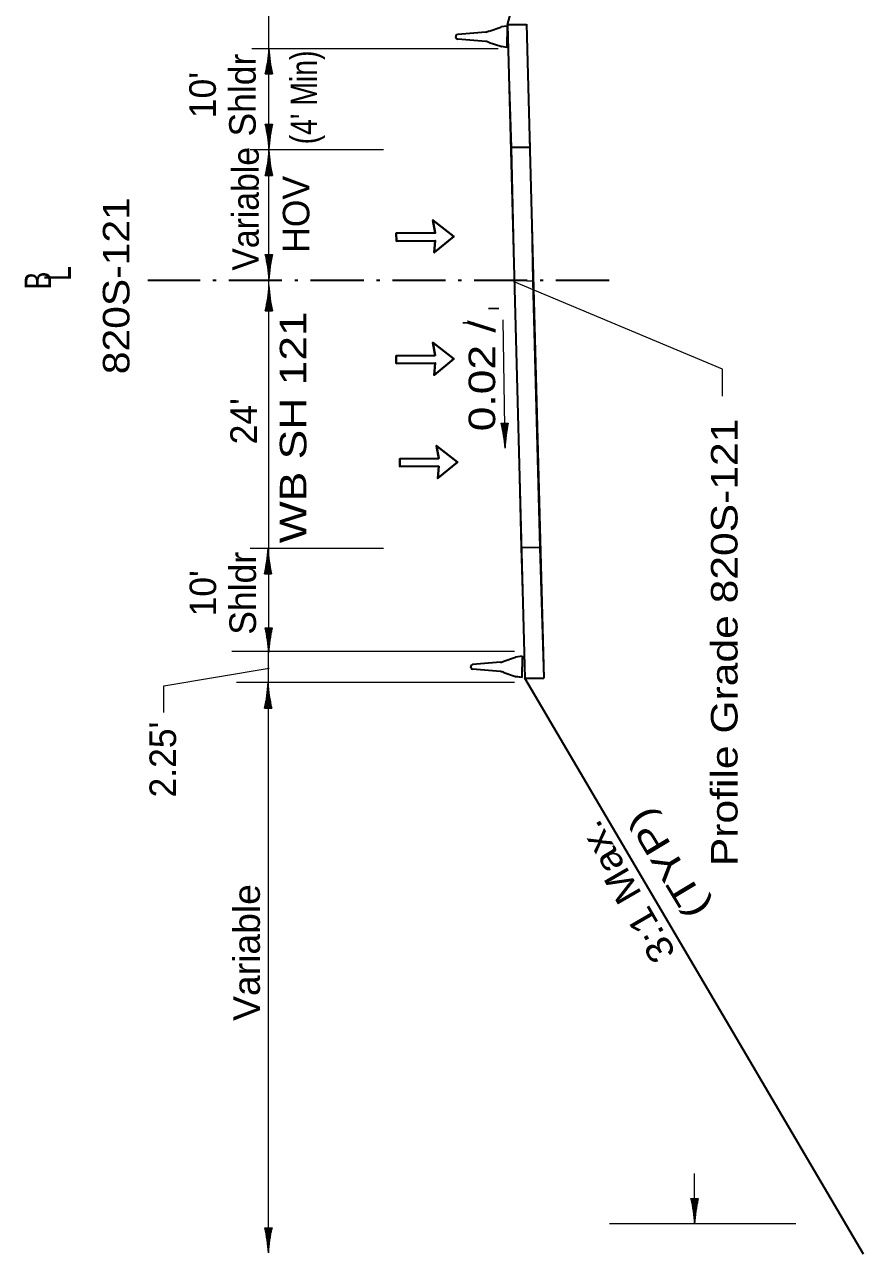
# Model space of a CAD drawing. Extents: x 2363427 to 2368559, y 6957299 to 6980140.
# Drawn here: x 2364081 to 2364523, y 6964609 to 6965257 of the extents above; entities that cross this region are included whole.
import ezdxf
from ezdxf.enums import TextEntityAlignment as Align

# ---------------------------------------------------------------- set-up
doc = ezdxf.new("R2010")
doc.units = 0
doc.header["$LTSCALE"] = 5.6
doc.linetypes.add('DOT_DASHED', pattern=[7.7, 5, -1.2, 0.3, -1.2])
for name, color, linetype, lineweight in [('1', 7, 'Continuous', 13), ('3', 7, 'Continuous', 35), ('4', 7, 'Continuous', 13), ('40', 7, 'Continuous', 35), ('8', 7, 'Continuous', 13)]:
    doc.layers.add(name, color=color, linetype=linetype, lineweight=lineweight)

msp = doc.modelspace()

# ---------------------------------------------------------------- linework, layer by layer
at = {"layer": '1'}
for p, q in [((2364432.195, 6964638.052), (2364436.025, 6964638.052)), ((2364432.545, 6964638.052), (2364432.545, 6964636.466)), ((2364433.045, 6964638.052), (2364433.045, 6964633.776)), ((2364433.545, 6964638.052), (2364433.545, 6964630.702)), ((2364434.045, 6964638.052), (2364434.045, 6964625.488)), ((2364434.545, 6964638.052), (2364434.545, 6964629.442)), ((2364435.045, 6964638.052), (2364435.045, 6964633.19)), ((2364435.545, 6964638.052), (2364435.545, 6964635.67))]:
    msp.add_line(p, q, dxfattribs=at)
for centre, start, end in [((2364361.987, 6964621.158), 2.84356, 13.52961), ((2364506.234, 6964621.158), 166.47039, 177.15644)]:
    msp.add_arc(centre, 72.212, start, end, dxfattribs=at)
at = {"layer": '3'}
for p, q in [((2364323.944, 6965253.408), (2364309.24, 6965252.173)), ((2364325.732, 6965253.937), (2364331.846, 6965255.978)), ((2364332.01, 6965256.044), (2364332.02, 6965256.068)), ((2364335.283, 6965256.556), (2364332.02, 6965256.068)), ((2364335.283, 6965256.556), (2364332.217, 6965256.098)), ((2364335.283, 6965256.556), (2364335.283, 6965250.932)), ((2364345.398, 6965257.606), (2364354.58, 6964912.562)), ((2364308.213, 6965251.332), (2364308.213, 6965250.932)), ((2364308.213, 6965250.531), (2364308.213, 6965250.932)), ((2364323.944, 6965248.455), (2364309.24, 6965249.69)), ((2364325.732, 6965247.926), (2364331.846, 6965245.884)), ((2364332.01, 6965245.82), (2364332.02, 6965245.794)), ((2364335.283, 6965245.306), (2364332.02, 6965245.794)), ((2364335.283, 6965245.306), (2364332.217, 6965245.766)), ((2364335.283, 6965245.306), (2364335.283, 6965250.932)), ((2364347.589, 6965192.45), (2364337.588, 6965192.45)), ((2364343.957, 6964943.654), (2364343.793, 6964943.962)), ((2364333.538, 6964921.55), (2364339.651, 6964923.592)), ((2364339.816, 6964923.656), (2364339.826, 6964923.682)), ((2364343.088, 6964924.17), (2364339.826, 6964923.682)), ((2364343.088, 6964924.17), (2364340.022, 6964923.71)), ((2364343.088, 6964924.17), (2364343.088, 6964918.544)), ((2364316.018, 6964918.945), (2364316.018, 6964918.544)), ((2364316.018, 6964918.144), (2364316.018, 6964918.544)), ((2364331.749, 6964921.021), (2364317.046, 6964919.786)), ((2364331.749, 6964916.068), (2364317.046, 6964917.303)), ((2364333.538, 6964915.539), (2364339.651, 6964913.498)), ((2364343.088, 6964912.92), (2364343.088, 6964918.544)), ((2364339.816, 6964913.432), (2364339.826, 6964913.408)), ((2364343.088, 6964912.92), (2364339.826, 6964913.408)), ((2364343.088, 6964912.92), (2364340.022, 6964913.378)), ((2364344.576, 6964912.562), (2364354.579, 6964912.562)), ((2364523.11, 6964608.848), (2364344.609, 6964912.542))]:
    msp.add_line(p, q, dxfattribs=at)
at = {"layer": '3', "linetype": 'DOT_DASHED'}
msp.add_line((2364388.994, 6965122.286), (2364145.785, 6965122.286), dxfattribs=at)
at = {"layer": '3', "lineweight": 13}
for p, q in [((2364448.885, 6965075.502), (2364338.95, 6965121.619)), ((2364448.885, 6965061.274), (2364448.885, 6965075.502)), ((2364154.244, 6964908.479), (2364209.681, 6964917.845)), ((2364154.244, 6964894.43), (2364154.244, 6964908.479))]:
    msp.add_line(p, q, dxfattribs=at)
at = {"layer": '3'}
for points in [[(2364335.405, 6965257.22), (2364342.45, 6965282.965), (2364333.872, 6965304.046)], [(2364345.408, 6965257.22), (2364335.405, 6965257.22), (2364344.576, 6964912.562)]]:
    msp.add_lwpolyline(points, dxfattribs=at)
at = {"layer": '3', "lineweight": 13}
for points in [[(2364337.588, 6965192.45), (2364347.589, 6965192.45), (2364345.408, 6965257.22), (2364335.405, 6965257.22)], [(2364339.137, 6965122.445), (2364348.845, 6965121.956), (2364347.589, 6965192.45), (2364337.588, 6965192.45)], [(2364342.471, 6964981.594), (2364352.472, 6964981.594), (2364348.845, 6965121.956), (2364339.137, 6965122.445)], [(2364344.576, 6964912.562), (2364354.58, 6964912.562), (2364352.472, 6964981.594), (2364342.471, 6964981.594)]]:
    msp.add_lwpolyline(points, close=True, dxfattribs=at)
at = {"layer": '3'}
for centre, radius, start, end in [((2364309.361, 6965250.979), 1.2, 95.72178, 162.90786), ((2364323.445, 6965258.384), 5, 275.73538, 297.22872), ((2364332.396, 6965254.911), 1.2, 98.51269, 117.22516), ((2364309.361, 6965250.884), 1.2, 197.09214, 264.27822), ((2364323.445, 6965243.48), 5, 62.77128, 84.26462), ((2364332.396, 6965246.952), 1.2, 242.77484, 261.48731), ((2364331.25, 6964925.997), 5, 275.73538, 297.22872), ((2364340.201, 6964922.524), 1.2, 98.51269, 117.22516), ((2364317.166, 6964918.592), 1.2, 95.72178, 162.90786), ((2364317.166, 6964918.497), 1.2, 197.09214, 264.27822), ((2364331.25, 6964911.093), 5, 62.77128, 84.26462), ((2364340.201, 6964914.565), 1.2, 242.77484, 261.48731)]:
    msp.add_arc(centre, radius, start, end, dxfattribs=at)
at = {"layer": '4'}
for p, q in [((2364209.647, 6964926.644), (2364209.647, 6965291.985)), ((2364209.583, 6965231.306), (2364209.583, 6965243.87)), ((2364210.083, 6965231.306), (2364210.083, 6965239.914)), ((2364330.544, 6965244.616), (2364233.477, 6965244.616)), ((2364208.083, 6965231.306), (2364208.083, 6965232.89)), ((2364208.583, 6965231.306), (2364208.583, 6965235.582)), ((2364209.083, 6965231.306), (2364209.083, 6965238.656)), ((2364210.583, 6965231.306), (2364210.583, 6965236.168)), ((2364211.083, 6965231.306), (2364211.083, 6965233.686)), ((2364207.733, 6965231.306), (2364211.563, 6965231.306)), ((2364207.733, 6965204.804), (2364211.563, 6965204.804)), ((2364208.083, 6965204.804), (2364208.083, 6965203.218)), ((2364208.583, 6965204.804), (2364208.583, 6965200.528)), ((2364209.083, 6965204.804), (2364209.083, 6965197.454)), ((2364209.583, 6965204.804), (2364209.583, 6965192.24)), ((2364210.083, 6965204.804), (2364210.083, 6965196.194)), ((2364210.583, 6965204.804), (2364210.583, 6965199.942)), ((2364211.083, 6965204.804), (2364211.083, 6965202.422)), ((2364269.98, 6965191.292), (2364199.828, 6965191.292)), ((2364209.583, 6965177.66), (2364209.583, 6965190.224)), ((2364208.583, 6965177.66), (2364208.583, 6965181.936)), ((2364209.083, 6965177.66), (2364209.083, 6965185.01)), ((2364210.083, 6965177.66), (2364210.083, 6965186.27)), ((2364210.583, 6965177.66), (2364210.583, 6965182.522)), ((2364207.733, 6965177.66), (2364211.563, 6965177.66)), ((2364208.083, 6965177.66), (2364208.083, 6965179.246)), ((2364211.083, 6965177.66), (2364211.083, 6965180.042)), ((2364207.733, 6965136.08), (2364211.563, 6965136.08)), ((2364208.083, 6965136.08), (2364208.083, 6965134.494)), ((2364208.583, 6965136.08), (2364208.583, 6965131.804)), ((2364209.083, 6965136.08), (2364209.083, 6965128.73)), ((2364209.583, 6965136.08), (2364209.583, 6965123.516)), ((2364210.083, 6965136.08), (2364210.083, 6965127.47)), ((2364210.583, 6965136.08), (2364210.583, 6965131.218)), ((2364211.083, 6965136.08), (2364211.083, 6965133.698)), ((2364209.583, 6965106.334), (2364209.583, 6965118.898)), ((2364208.583, 6965106.334), (2364208.583, 6965110.61)), ((2364209.083, 6965106.334), (2364209.083, 6965113.684)), ((2364210.083, 6965106.334), (2364210.083, 6965114.942)), ((2364210.583, 6965106.334), (2364210.583, 6965111.196)), ((2364207.733, 6965106.334), (2364211.563, 6965106.334)), ((2364208.083, 6965106.334), (2364208.083, 6965107.918)), ((2364211.083, 6965106.334), (2364211.083, 6965108.714)), ((2364334.162, 6965033.826), (2364333.088, 6965101.542)), ((2364332.036, 6965047.106), (2364335.865, 6965047.166)), ((2364332.386, 6965047.11), (2364332.411, 6965045.526)), ((2364332.886, 6965047.118), (2364332.954, 6965042.842)), ((2364333.386, 6965047.126), (2364333.502, 6965039.778)), ((2364333.886, 6965047.134), (2364334.085, 6965034.572)), ((2364334.386, 6965047.142), (2364334.522, 6965038.534)), ((2364334.885, 6965047.15), (2364334.963, 6965042.29)), ((2364335.385, 6965047.158), (2364335.423, 6965044.778)), ((2364269.98, 6964980.954), (2364199.828, 6964980.954)), ((2364209.094, 6964967.642), (2364209.094, 6964980.206)), ((2364208.594, 6964967.642), (2364208.594, 6964974.992)), ((2364209.594, 6964967.642), (2364209.594, 6964976.252)), ((2364207.244, 6964967.642), (2364211.074, 6964967.642)), ((2364207.594, 6964967.642), (2364207.594, 6964969.228)), ((2364208.094, 6964967.642), (2364208.094, 6964971.918)), ((2364210.094, 6964967.642), (2364210.094, 6964972.504)), ((2364210.594, 6964967.642), (2364210.594, 6964970.024)), ((2364207.572, 6964939.223), (2364211.402, 6964939.223)), ((2364207.922, 6964939.223), (2364207.922, 6964937.638)), ((2364208.422, 6964939.223), (2364208.422, 6964934.947)), ((2364208.922, 6964939.223), (2364208.922, 6964931.873)), ((2364209.422, 6964939.223), (2364209.422, 6964926.659)), ((2364209.922, 6964939.223), (2364209.922, 6964930.614)), ((2364210.422, 6964939.223), (2364210.422, 6964934.361)), ((2364210.922, 6964939.223), (2364210.922, 6964936.842)), ((2364339.076, 6964926.644), (2364190.153, 6964926.644)), ((2364209.35, 6964622.138), (2364209.347, 6964926.644)), ((2364339.076, 6964910.253), (2364192.496, 6964910.253)), ((2364209.124, 6964896.778), (2364209.124, 6964909.342)), ((2364208.624, 6964896.778), (2364208.624, 6964904.128)), ((2364209.624, 6964896.778), (2364209.624, 6964905.388)), ((2364207.274, 6964896.778), (2364211.104, 6964896.778)), ((2364207.624, 6964896.778), (2364207.624, 6964898.364)), ((2364208.124, 6964896.778), (2364208.124, 6964901.055)), ((2364210.124, 6964896.778), (2364210.124, 6964901.64)), ((2364210.624, 6964896.778), (2364210.624, 6964899.16)), ((2364434.11, 6964624.74), (2364434.11, 6964651.32)), ((2364487.486, 6964624.796), (2364389.289, 6964624.796)), ((2364207.434, 6964622.714), (2364211.264, 6964622.714)), ((2364207.784, 6964622.714), (2364207.784, 6964621.129)), ((2364208.284, 6964622.714), (2364208.284, 6964618.438)), ((2364208.784, 6964622.714), (2364208.784, 6964615.364)), ((2364209.284, 6964622.714), (2364209.284, 6964610.15)), ((2364209.784, 6964622.714), (2364209.784, 6964614.104)), ((2364210.284, 6964622.714), (2364210.284, 6964617.852)), ((2364210.784, 6964622.714), (2364210.784, 6964620.332))]:
    msp.add_line(p, q, dxfattribs=at)
at = {"layer": '4', "lineweight": 25}
for p, q in [((2364325.351, 6965107.486), (2364330.919, 6965107.486)), ((2364317.926, 6965100.066), (2364311.893, 6965100.066))]:
    msp.add_line(p, q, dxfattribs=at)
at = {"layer": '4'}
msp.add_lwpolyline([(2364235.82, 6965244.616), (2364221.758, 6965244.616), (2364200.716, 6965244.616)], dxfattribs=at)
for centre, start, end in [((2364137.525, 6965248.2), 346.47039, 357.15644), ((2364281.772, 6965248.2), 182.84356, 193.52961), ((2364137.524, 6965187.911), 2.84356, 13.52961), ((2364281.771, 6965187.911), 166.47039, 177.15644), ((2364137.525, 6965194.555), 346.47039, 357.15644), ((2364281.772, 6965194.555), 182.84356, 193.52961), ((2364137.525, 6965119.187), 2.84356, 13.52961), ((2364281.772, 6965119.187), 166.47039, 177.15644), ((2364137.525, 6965123.228), 346.47039, 357.15644), ((2364281.772, 6965123.228), 182.84356, 193.52961), ((2364262.105, 6965029.101), 3.7522, 14.43825), ((2364406.334, 6965031.388), 167.37903, 178.06508), ((2364137.036, 6964984.537), 346.47039, 357.15644), ((2364281.283, 6964984.537), 182.84356, 193.52961), ((2364137.364, 6964922.33), 2.84356, 13.52961), ((2364281.611, 6964922.33), 166.47039, 177.15644), ((2364137.066, 6964913.673), 346.47039, 357.15644), ((2364281.313, 6964913.673), 182.84356, 193.52961), ((2364137.226, 6964605.821), 2.84356, 13.52961), ((2364281.473, 6964605.821), 166.47039, 177.15644)]:
    msp.add_arc(centre, 72.212, start, end, dxfattribs=at)
at = {"layer": '40'}
for p, q in [((2364297.35, 6965143.338), (2364276.845, 6965143.144)), ((2364297.312, 6965078.762), (2364276.807, 6965078.568)), ((2364299.199, 6965024.374), (2364278.694, 6965024.18))]:
    msp.add_line(p, q, dxfattribs=at)
for points in [[(2364297.35, 6965143.338), (2364296.818, 6965137.024), (2364307.205, 6965145.558), (2364296.105, 6965154.162), (2364297.313, 6965147.434)], [(2364297.313, 6965147.434), (2364276.808, 6965147.238), (2364276.845, 6965143.144)], [(2364297.312, 6965078.762), (2364296.78, 6965072.448), (2364307.167, 6965080.982), (2364296.067, 6965089.586), (2364297.275, 6965082.858)], [(2364297.275, 6965082.858), (2364276.77, 6965082.662), (2364276.807, 6965078.568)], [(2364299.199, 6965024.374), (2364298.667, 6965018.06), (2364309.054, 6965026.594), (2364297.954, 6965035.196), (2364299.162, 6965028.47)], [(2364299.162, 6965028.47), (2364278.657, 6965028.274), (2364278.694, 6965024.18)]]:
    msp.add_lwpolyline(points, dxfattribs=at)
at = {"layer": '8', "lineweight": 40}
for points in [[(2364307.205, 6965145.558), (2364296.818, 6965137.024), (2364297.35, 6965143.338), (2364276.845, 6965143.144), (2364276.808, 6965147.238), (2364297.313, 6965147.434), (2364296.105, 6965154.162)], [(2364307.167, 6965080.982), (2364296.78, 6965072.448), (2364297.312, 6965078.762), (2364276.807, 6965078.568), (2364276.77, 6965082.662), (2364297.275, 6965082.858), (2364296.067, 6965089.586)], [(2364309.054, 6965026.594), (2364298.667, 6965018.06), (2364299.199, 6965024.374), (2364278.694, 6965024.18), (2364278.657, 6965028.274), (2364299.162, 6965028.47), (2364297.954, 6965035.196)]]:
    msp.add_lwpolyline(points, close=True, dxfattribs=at)

# ---------------------------------------------------------------- texts
at = {"layer": '3', "width": 0.75}
msp.add_text('B', height=14, rotation=90, dxfattribs=at).set_placement((2364094.802, 6965122.315), align=Align.CENTER)
at = {"layer": '4'}
for s, p in [('Shldr', (2364202.663, 6965220.135)), ("10'", (2364181.663, 6965220.137)), ('HOV', (2364230.964, 6965157.222)), ("24' ", (2364203.303, 6965050.703)), ('Shldr', (2364202.812, 6964957.345)), ("10'", (2364181.812, 6964957.344)), ("2.25' ", (2364160.667, 6964872.242))]:
    msp.add_text(s, height=14, rotation=90, dxfattribs=at).set_placement(p, align=Align.CENTER)
for s, rotation, width, p in [("(4' Min) ", 90, 0.8, (2364235.04, 6965220.987)), ('Variable ', 90, 0.95, (2364204.28, 6965162.629)), ('820S-121', 90, 1.15, (2364136.077, 6965119.59)), ('L', 90, 0.75, (2364105.219, 6965126.04)), (' WB SH 121', 90, 1.25, (2364229.383, 6965041.673)), ('0.02 /', 90, 1.25, (2364328.962, 6965072.074)), ('Profile Grade 820S-121', 90, 1.2, (2364456.732, 6964931.459)), ('3:1 Max.', 120.088, 1.15, (2364403.929, 6964803.351)), ('(TYP)', 121.08, 1.3, (2364425.904, 6964818.276)), ('Variable', 90, 1.05, (2364204.873, 6964767.895))]:
    msp.add_text(s, height=14, rotation=rotation, dxfattribs=dict(at, width=width)).set_placement(p, align=Align.CENTER)

doc.saveas('drawing.dxf')
